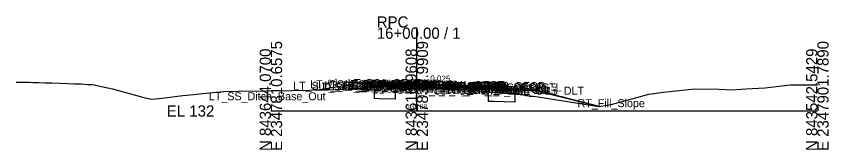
# Model space of a CAD drawing. Extents: x -26 to 203, y -10 to 7538.
# Drawn here: x 0 to 202.8, y 2490.3 to 2523.7 of the extents above; entities that cross this region are included whole.
import ezdxf

# ---------------------------------------------------------------- set-up
doc = ezdxf.new("R2010")
doc.units = 0
for name, color, linetype in [('Default', 7, 'Continuous'), ('Exist CMT Pavement', 7, 'Continuous'), ('Exist Cross Section Cell', 7, 'Continuous'), ('Exist XS Center Line Elevation Label', 7, 'Continuous'), ('Exist XS Ground Line', 7, 'Continuous'), ('Prop CMT Pvmt Course 1', 7, 'Continuous'), ('Prop CMT Pvmt Course 1 Wedge', 7, 'Continuous'), ('Prop CMT Pvmt Course 2', 7, 'Continuous'), ('Prop CMT Pvmt Course 2 Wedge', 7, 'Continuous'), ('Prop CMT Pvmt Course 3', 7, 'Continuous'), ('Prop CMT Pvmt Course 3 Wedge', 7, 'Continuous'), ('Prop CMT Pvmt Surface', 7, 'Continuous'), ('Prop CMT Pvmt Surface Shoulder', 7, 'Continuous'), ('Prop CMT Pvmt Wedge Surface 1', 7, 'Continuous'), ('Prop CMT Pvmt Wedge Surface 2', 7, 'Continuous'), ('Prop CMT Pvmt Wedge Surface 3', 7, 'Continuous'), ('Prop CMT Shld Paved Course 1', 7, 'Continuous'), ('Prop CMT Shld Paved Course 2', 7, 'Continuous'), ('Prop CMT Shld Paved Course 3', 7, 'Continuous'), ('Prop CMT Slope Grass', 7, 'Continuous'), ('Prop CMT Subgrade Earthwork', 7, 'Continuous'), ('Prop Road Sect_ Recs - UC (Outline)', 7, 'Continuous'), ('Prop XS Earthwork Shape', 7, 'Continuous'), ('Prop XS SE Text', 7, 'Continuous'), ('Prop XS Side Slope Text', 7, 'Continuous'), ('Scratch_Level_0', 7, 'Continuous')]:
    doc.layers.add(name, color=color, linetype=linetype)

msp = doc.modelspace()

# ---------------------------------------------------------------- linework, layer by layer
at = {"layer": 'Exist CMT Pavement'}
for q in [(97.89, 2506.22), (112, 2505.27)]:
    msp.add_line((100, 2506.08), q, dxfattribs=at)
at = {"layer": 'Exist Cross Section Cell'}
for p, q in [((100, 2500), (100, 2520.85)), ((63.57, 2500), (100, 2500)), ((100, 2500), (200, 2500))]:
    msp.add_line(p, q, dxfattribs=at)
at = {"layer": 'Exist XS Ground Line'}
msp.add_lwpolyline([(0, 2507.23), (0.95, 2507.21), (2.03, 2507.2), (3.29, 2507.17), (4.29, 2507.15), (5.54, 2507.12), (7.2, 2507.07), (7.53, 2507.07), (7.85, 2507.06), (8.88, 2507.03), (11.05, 2506.96), (12.77, 2506.89), (14.52, 2506.82), (16.27, 2506.76), (17.8, 2506.64), (18.35, 2506.6), (19.03, 2506.62), (22.44, 2505.9), (24.05, 2505.5), (31.85, 2503.41), (33.77, 2502.93), (35.59, 2503.15), (37.7, 2503.4), (41.59, 2503.88), (44.33, 2504.13), (45.72, 2504.25), (51.7, 2504.9), (55.42, 2504.94), (62.51, 2505.02), (68.86, 2505.09), (77.48, 2505.29), (80.02, 2505.36), (82.77, 2505.55), (94.63, 2506.22), (95.55, 2506.25), (95.93, 2506.26), (96.88, 2506.23), (97.27, 2506.23), (97.89, 2506.22), (98.25, 2506.2), (100, 2506.08), (100.59, 2506.05), (101.72, 2505.98), (102.94, 2505.89), (104.34, 2505.8), (104.72, 2505.77), (105.06, 2505.75), (106.51, 2505.66), (108.1, 2505.55), (108.44, 2505.52), (110.03, 2505.41), (111.8, 2505.28), (114.16, 2505.14), (115.12, 2505.05), (115.53, 2505.02), (116.68, 2504.94), (117.87, 2504.86), (118.19, 2504.83), (125.79, 2504.16), (130.3, 2503.52), (145.45, 2501.14), (147.54, 2501.44), (148.51, 2501.63), (154.34, 2503.23), (157.92, 2504.2), (161.6, 2504.7), (169.42, 2505.54), (175.45, 2505.42), (178.6, 2505.32), (180.98, 2505.47), (182.11, 2505.56), (186.89, 2505.82), (193.33, 2506.55), (197.25, 2506.57), (200, 2506.58)], dxfattribs=at)
at = {"layer": 'Prop CMT Pvmt Course 1'}
for p, q in [((100, 2506.76), (96, 2506.86)), ((96, 2506.86), (96, 2506.61)), ((96, 2506.61), (97.89, 2506.57)), ((97.89, 2506.57), (97.89, 2506.69)), ((97.89, 2506.69), (100, 2506.64)), ((100, 2506.51), (100, 2506.76)), ((100, 2506.76), (112, 2506.46)), ((100, 2506.51), (100, 2506.76)), ((100, 2506.64), (100, 2506.51)), ((112, 2506.34), (100, 2506.64)), ((100, 2506.64), (100, 2506.51)), ((100, 2506.51), (100, 2506.51)), ((100, 2506.51), (100, 2506.51)), ((112, 2506.46), (112, 2506.21)), ((112, 2506.21), (112, 2506.34)), ((112, 2506.21), (112, 2506.21))]:
    msp.add_line(p, q, dxfattribs=at)
at = {"layer": 'Prop CMT Pvmt Course 1 Wedge'}
for q in [(97.89, 2506.69), (112, 2506.34)]:
    msp.add_line((100, 2506.64), q, dxfattribs=at)
at = {"layer": 'Prop CMT Pvmt Course 2'}
for p, q in [((97.89, 2506.57), (96, 2506.61)), ((96, 2506.61), (96, 2506.28)), ((96, 2506.28), (97.89, 2506.23)), ((97.89, 2506.23), (97.89, 2506.57)), ((112, 2505.88), (112, 2506.21)), ((112, 2506.21), (112, 2506.21)), ((112, 2506.21), (112, 2505.88)), ((112, 2505.88), (112, 2505.88))]:
    msp.add_line(p, q, dxfattribs=at)
at = {"layer": 'Prop CMT Pvmt Course 2 Wedge'}
for q in [(97.89, 2506.57), (112, 2506.21)]:
    msp.add_line((100, 2506.51), q, dxfattribs=at)
at = {"layer": 'Prop CMT Pvmt Course 3'}
for p, q in [((97.89, 2506.23), (96, 2506.28)), ((96, 2506.28), (96, 2505.95)), ((96, 2505.95), (97.89, 2505.9)), ((97.89, 2505.9), (97.89, 2506.23)), ((112, 2505.88), (112, 2505.88)), ((112, 2505.88), (112, 2505.55)), ((112, 2505.55), (112, 2505.88)), ((112, 2505.55), (112, 2505.55))]:
    msp.add_line(p, q, dxfattribs=at)
at = {"layer": 'Prop CMT Pvmt Course 3 Wedge'}
for q in [(97.89, 2506.23), (112, 2505.88)]:
    msp.add_line((100, 2506.18), q, dxfattribs=at)
at = {"layer": 'Prop CMT Pvmt Surface'}
for q in [(96, 2506.86), (112, 2506.46)]:
    msp.add_line((100, 2506.76), q, dxfattribs=at)
at = {"layer": 'Prop CMT Pvmt Surface Shoulder'}
for p, q in [((96, 2506.86), (92, 2506.96)), ((112, 2506.46), (122, 2506.21))]:
    msp.add_line(p, q, dxfattribs=at)
at = {"layer": 'Prop CMT Pvmt Wedge Surface 1'}
for p, q in [((96, 2506.61), (96, 2506.86)), ((97.89, 2506.57), (96, 2506.61)), ((100, 2506.64), (97.89, 2506.69)), ((97.89, 2506.69), (97.89, 2506.57)), ((100, 2506.64), (112, 2506.34)), ((112, 2506.21), (112, 2506.46)), ((112, 2506.34), (112, 2506.21)), ((112, 2506.21), (112, 2506.21))]:
    msp.add_line(p, q, dxfattribs=at)
at = {"layer": 'Prop CMT Pvmt Wedge Surface 2'}
for p, q in [((96, 2506.61), (96, 2506.86)), ((100, 2506.51), (96, 2506.61)), ((100, 2506.51), (112, 2506.21)), ((112, 2506.21), (112, 2506.46))]:
    msp.add_line(p, q, dxfattribs=at)
at = {"layer": 'Prop CMT Pvmt Wedge Surface 3'}
for p, q in [((96, 2506.28), (96, 2506.86)), ((100, 2506.18), (96, 2506.28)), ((100, 2506.18), (112, 2505.88)), ((112, 2505.88), (112, 2506.46))]:
    msp.add_line(p, q, dxfattribs=at)
at = {"layer": 'Prop CMT Shld Paved Course 1'}
for p, q in [((92, 2506.96), (91.76, 2506.72)), ((91.76, 2506.72), (96, 2506.61)), ((96, 2506.86), (92, 2506.96)), ((96, 2506.61), (96, 2506.86)), ((112, 2506.46), (122, 2506.21)), ((112, 2506.21), (112, 2506.46)), ((122.26, 2505.96), (112, 2506.21)), ((122, 2506.21), (122.26, 2505.96))]:
    msp.add_line(p, q, dxfattribs=at)
at = {"layer": 'Prop CMT Shld Paved Course 2'}
for p, q in [((91.76, 2506.72), (91.43, 2506.39)), ((91.43, 2506.39), (96, 2506.28)), ((96, 2506.61), (91.76, 2506.72)), ((96, 2506.28), (96, 2506.61)), ((112, 2506.21), (122.26, 2505.96)), ((112, 2505.88), (112, 2506.21)), ((122.6, 2505.62), (112, 2505.88)), ((122.26, 2505.96), (122.6, 2505.62))]:
    msp.add_line(p, q, dxfattribs=at)
at = {"layer": 'Prop CMT Shld Paved Course 3'}
for p, q in [((90.93, 2506.41), (90.61, 2506.08)), ((90.61, 2506.08), (96, 2505.95)), ((91.43, 2506.39), (90.93, 2506.41)), ((96, 2506.28), (91.43, 2506.39)), ((96, 2505.95), (96, 2506.28)), ((112, 2505.88), (122.6, 2505.62)), ((112, 2505.55), (112, 2505.88)), ((123.44, 2505.26), (112, 2505.55)), ((122.6, 2505.62), (123.1, 2505.6)), ((123.1, 2505.6), (123.44, 2505.26))]:
    msp.add_line(p, q, dxfattribs=at)
at = {"layer": 'Prop CMT Slope Grass'}
for p, q in [((84, 2506.68), (75.36, 2505.24)), ((92, 2506.96), (84, 2506.68)), ((122, 2506.21), (126, 2506.07)), ((126, 2506.07), (145.64, 2501.16))]:
    msp.add_line(p, q, dxfattribs=at)
at = {"layer": 'Prop CMT Subgrade Earthwork'}
for p, q in [((90.61, 2506.08), (81.72, 2506.3)), ((96, 2505.95), (90.61, 2506.08)), ((97.89, 2505.9), (96, 2505.95)), ((97.89, 2505.9), (97.89, 2506.22)), ((112, 2505.55), (112, 2505.27)), ((112, 2505.55), (123.44, 2505.26)), ((112, 2505.55), (112, 2505.55)), ((123.44, 2505.26), (129.9, 2505.1))]:
    msp.add_line(p, q, dxfattribs=at)
at = {"layer": 'Prop Road Sect_ Recs - UC (Outline)'}
for points in [[(94.63, 2505.98), (94.63, 2502.98), (90.61, 2503.08), (89.41, 2503.11), (89.49, 2505.93), (91.93, 2506.05)], [(124.43, 2505.23), (124.48, 2502.23), (119.12, 2502.39), (117.86, 2502.41), (117.86, 2505.4), (120.42, 2505.35)]]:
    msp.add_lwpolyline(points, close=True, dxfattribs=at)
at = {"layer": 'Prop XS Earthwork Shape'}
for points in [[(91.68, 2506.06), (90.61, 2506.08), (81.72, 2506.3), (75.36, 2505.24), (77.48, 2505.29), (80.02, 2505.36), (82.77, 2505.55)], [(97.89, 2505.9), (96, 2505.95), (91.68, 2506.06), (94.63, 2506.22), (95.55, 2506.25), (95.93, 2506.26), (96.88, 2506.23), (97.27, 2506.23), (97.89, 2506.22)], [(100, 2506.08), (97.89, 2506.22), (98.25, 2506.2)], [(100, 2506.08), (111.45, 2505.31), (110.03, 2505.41), (108.44, 2505.52), (108.1, 2505.55), (106.51, 2505.66), (105.06, 2505.75), (104.72, 2505.77), (104.34, 2505.8), (102.94, 2505.89), (101.72, 2505.98), (100.59, 2506.05)], [(111.45, 2505.31), (111.8, 2505.28), (112, 2505.27)], [(112, 2505.55), (112, 2505.27), (114.16, 2505.14), (115.12, 2505.05), (115.53, 2505.02), (116.68, 2504.94), (117.87, 2504.86), (118.19, 2504.83), (125.79, 2504.16), (130.3, 2503.52), (145.45, 2501.14), (145.64, 2501.16), (129.9, 2505.1), (123.44, 2505.26)]]:
    msp.add_lwpolyline(points, close=True, dxfattribs=at)

# ---------------------------------------------------------------- texts
at = {"layer": 'Default'}
msp.add_text('-', height=0.0001, dxfattribs=at).set_placement((63.57, 2500))
at = {"layer": 'Exist Cross Section Cell'}
for s, p in [('RPC', (90, 2520.85)), ('16+00.00 / 1', (90, 2518.05)), ('EL 132', (37.57, 2498.6))]:
    msp.add_text(s, height=2.8, dxfattribs=at).set_placement(p)
for s, p in [('E 2347810.6575', (66.37, 2490)), ('E 2347834.9909', (102.8, 2490)), ('E 2347901.7890', (202.8, 2490)), ('N 843644.0700', (63.57, 2490)), ('N 843616.9608', (100, 2490)), ('N 843542.5429', (200, 2490))]:
    msp.add_text(s, height=2.8, rotation=90, dxfattribs=at).set_placement(p)
at = {"layer": 'Exist XS Center Line Elevation Label'}
msp.add_text('138.08', height=1.2, dxfattribs=at).set_placement((97.51, 2500.48))
at = {"layer": 'Prop XS SE Text'}
msp.add_text('0.025', height=1.5, rotation=358.5679, dxfattribs=at).set_placement((103.34, 2507.43))
at = {"layer": 'Prop XS Side Slope Text'}
for s, rotation, p in [('6:1', 9.4623, (77.84, 2506.23)), ('4:1', 345.9638, (132.05, 2504.62))]:
    msp.add_text(s, height=1.5, rotation=rotation, dxfattribs=at).set_placement(p)
at = {"layer": 'Scratch_Level_0'}
for s, p in [('LT_Sub_OSS_DLT', (69.12, 2505.3)), ('LT_GS_OS_CTL', (73.37, 2505.68)), ('LT_Sub_Trench_Out', (74.81, 2505.08)), ('LT_PS3_Shelf_Out', (76.92, 2505.41)), ('LT_PS3_OEOP', (81.67, 2505.39)), ('LT_PS2_OEOP', (81.99, 2505.72)), ('LT_PS1_OEOP', (82.8, 2505.96)), ('LT_PV_Sub_Tie_Out', (82.84, 2505.22)), ('LT_PV_OEEOP_EG', (85.43, 2505.22)), ('LT_PV2_OEOT', (86.17, 2505.61)), ('LT_PV3_OEOT', (86.17, 2505.28)), ('LT_PV1_OEOT', (86.74, 2505.86)), ('LT_PV2_OEEOP', (87.2, 2505.57)), ('LT_PV3_OEEOP', (87.2, 2505.23)), ('LT_PV1_OEEOP', (87.76, 2505.69)), ('RT_PV_IEEOP_EG', (88.14, 2505.08)), ('LT_PV_IEEOP_EG', (88.19, 2505.08)), ('RT_PV2_IEEOP', (89.91, 2505.51)), ('RT_PV3_IEEOP', (89.91, 2505.18)), ('LT_PV2_IEEOP', (89.95, 2505.51)), ('LT_PV3_IEEOP', (89.95, 2505.18)), ('RT_PV1_IEEOP', (90.47, 2505.64)), ('LT_PV1_IEEOP', (90.52, 2505.64)), ('PV2_PGL', (93.91, 2505.51)), ('PV1_PGL', (94.47, 2505.76)), ('RT_PV2_OEEOP', (101.26, 2505.21)), ('RT_PV1_OEEOP', (101.83, 2505.34)), ('RT_PV2_OEOT', (102.13, 2505.21)), ('RT_PV1_OEOT', (102.69, 2505.46)), ('RT_PS1_OEOP', (112.76, 2505.21)), ('LT_Sub_OEOT', (86.08, 2504.95)), ('LT_Sub_OEEOP', (87.1, 2504.9)), ('RT_PV_Sub_Tie_Out', (96.9, 2504.27)), ('RT_PV_OEEOP_EG', (99.49, 2504.27)), ('RT_Sub_OEEOP', (101.17, 2504.55)), ('RT_PV3_OEEOP', (101.26, 2504.88)), ('RT_Sub_OEOT', (102.03, 2504.55)), ('RT_PV3_OEOT', (102.13, 2504.88)), ('RT_Sub_Trench_Out', (107.6, 2504.26)), ('RT_PS3_Shelf_Out', (109.04, 2504.6)), ('RT_PS2_OEOP', (112.45, 2504.96)), ('RT_PS3_OEOP', (112.79, 2504.62)), ('RT_GS_OS_CTL', (115.32, 2504.89)), ('RT_Sub_OSS_DLT', (118.27, 2504.07)), ('LT_SS_Ditch_Base_Out', (48.08, 2502.68)), ('RT_Fill_Slope', (140.14, 2500.95))]:
    msp.add_text(s, height=2, dxfattribs=at).set_placement(p)

doc.saveas('drawing.dxf')
